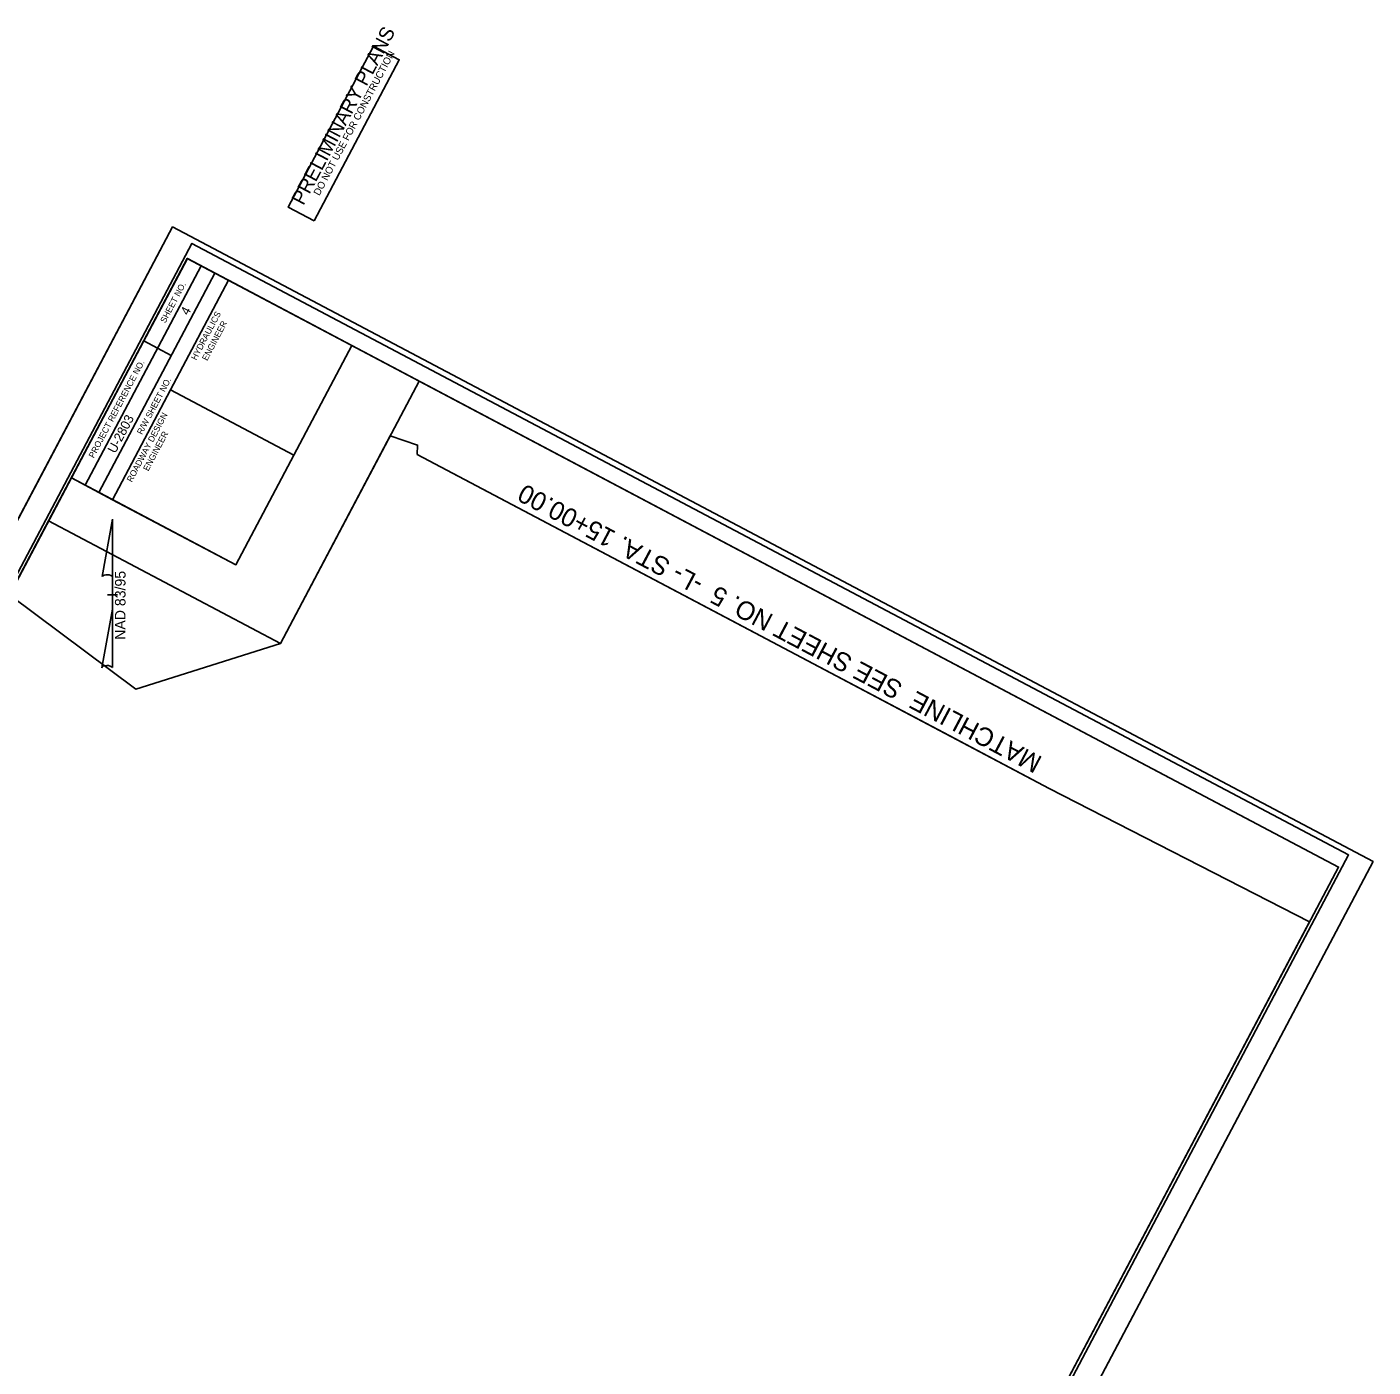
# Model space of a CAD drawing. Extents: x 1974781 to 1976536, y 777153 to 779314.
# Drawn here: x 1975451 to 1976536, y 778233 to 779314 of the extents above; entities that cross this region are included whole.
import ezdxf

# ---------------------------------------------------------------- set-up
doc = ezdxf.new("R2010")
doc.units = 0
for name, color, linetype in [('Matchline', 7, 'Continuous'), ('Matchline Text', 7, 'Continuous'), ('Old_Level_1', 7, 'Continuous'), ('Sheet Clip Boundary CELL', 7, 'Continuous'), ('Sheet Cutting Line CELL', 7, 'Continuous'), ('Sheet Data Field CELL', 7, 'Continuous'), ('Sheet North Arrow Point CELL', 7, 'Continuous'), ('Sheet Plan CELL', 7, 'Continuous'), ('Sheet Plan Layout CELL', 7, 'Continuous'), ('Sheet Plot Border Inside CELL', 7, 'Continuous'), ('Sheet Plot Border Outside CELL', 7, 'Continuous'), ('Sheet Sticker Preliminary CELL', 7, 'Continuous')]:
    doc.layers.add(name, color=color, linetype=linetype)

msp = doc.modelspace()

# ---------------------------------------------------------------- linework, layer by layer
at = {"layer": 'Matchline'}
msp.add_lwpolyline([(1976275.1, 778699.8), (1976019.4, 778834.9), (1975765.3, 778969.2)], dxfattribs=at)
at = {"layer": 'Old_Level_1'}
for p, q in [((1975511.4, 778870.7), (1975519.7, 778917)), ((1975519.8, 778917), (1975519.7, 778917)), ((1975519.8, 778917), (1975519.7, 778917)), ((1975519.8, 778917), (1975519.7, 778869.2)), ((1975519.6, 778844.4), (1975519.7, 778870.6)), ((1975519.7, 778869.2), (1975519.7, 778870.6)), ((1975515.7, 778856), (1975515.6, 778856)), ((1975515.7, 778856), (1975523.7, 778856)), ((1975519.2, 778856), (1975515.7, 778856)), ((1975519.6, 778844.4), (1975511.2, 778797.2)), ((1975519.6, 778797.4), (1975519.6, 778844.4))]:
    msp.add_line(p, q, dxfattribs=at)
for centre, start_param, end_param in [((1975515.6, 778870.2), 0.216388, 2.908219), ((1975515.4, 778797), 0.201328, 3.141593)]:
    msp.add_ellipse(centre, major_axis=(4.23, -0.04), ratio=0.461098, start_param=start_param, end_param=end_param, dxfattribs=at)
at = {"layer": 'Sheet Clip Boundary CELL'}
msp.add_lwpolyline([(1975830.7, 777354.5), (1976484.9, 778592.2), (1976275.1, 778699.8), (1976185.1, 778747.3), (1975765.3, 778969.2), (1975765.7, 778976.7), (1975743.6, 778984.1), (1975655.2, 778816.8), (1975538.6, 778780), (1975436.7, 778856), (1974902.4, 777845.2)], close=True, dxfattribs=at)
at = {"layer": 'Sheet Cutting Line CELL'}
for p, q in [((1975568.1, 779152.7), (1974781.3, 777664.3)), ((1975749.4, 777152.6), (1976536.2, 778640.9))]:
    msp.add_line(p, q, dxfattribs=at)
at = {"layer": 'Sheet North Arrow Point CELL'}
msp.add_line((1975519.2, 778856), (1975519.2, 778856), dxfattribs=at)
at = {"layer": 'Sheet Plan CELL'}
for p, q in [((1975497.6, 778944.4), (1975591.1, 779121.3)), ((1975508.7, 778938.6), (1975602.2, 779115.4)), ((1975508.7, 778938.6), (1975602.2, 779115.4)), ((1975545, 779060.8), (1975567.1, 779049.1)), ((1975566.5, 779021.2), (1975665.9, 778968.6)), ((1975508.7, 778938.6), (1975519.7, 778932.7))]:
    msp.add_line(p, q, dxfattribs=at)
for points in [[(1975580, 779127.2), (1974879, 777801), (1975807.3, 777310.3), (1976508.3, 778636.4)], [(1975486.5, 778950.3), (1975580, 779127.2), (1975602.2, 779115.4), (1975508.7, 778938.6)], [(1975566.5, 779021.2), (1975613.2, 779109.6), (1975712.7, 779057), (1975666, 778968.6)], [(1975807.3, 777310.3), (1974879, 777801), (1975486.5, 778950.3), (1975619.2, 778880.2), (1975712.7, 779057), (1976508.3, 778636.4)], [(1975519.7, 778932.7), (1975566.5, 779021.2), (1975666, 778968.6), (1975619.2, 778880.2)]]:
    msp.add_lwpolyline(points, close=True, dxfattribs=at)
at = {"layer": 'Sheet Plan Layout CELL'}
for points in [[(1975655.2, 778816.8), (1975767, 779028.3), (1975580.1, 779127.2), (1975468.2, 778915.6)], [(1974879, 777801), (1975807.3, 777310.3), (1976508.3, 778636.4), (1975767, 779028.3), (1975655.2, 778816.8), (1975468.2, 778915.6)]]:
    msp.add_lwpolyline(points, close=True, dxfattribs=at)
at = {"layer": 'Sheet Plot Border Inside CELL'}
msp.add_lwpolyline([(1975737.8, 777173.4), (1976516.4, 778646.3), (1975583.7, 779139.4), (1974805.1, 777666.5)], close=True, dxfattribs=at)
at = {"layer": 'Sheet Plot Border Outside CELL'}
msp.add_lwpolyline([(1975749.4, 777152.6), (1976536.2, 778640.9), (1975568.1, 779152.7), (1974781.3, 777664.3)], close=True, dxfattribs=at)
at = {"layer": 'Sheet Sticker Preliminary CELL'}
msp.add_lwpolyline([(1975682.2, 779157.5), (1975661.4, 779168.5), (1975730.1, 779298.5), (1975750.9, 779287.5)], close=True, dxfattribs=at)

# ---------------------------------------------------------------- texts
at = {"layer": 'Matchline Text'}
msp.add_text('MATCHLINE  SEE SHEET NO. 5  -L- STA. 15+00.00', height=15, rotation=152.1381, dxfattribs=at).set_placement((1976270.3, 778724.8))
at = {"layer": 'Old_Level_1'}
msp.add_text('NAD 83/95', height=8.5, rotation=89.9041, dxfattribs=at).set_placement((1975530.1, 778819.7))
at = {"layer": 'Sheet Data Field CELL'}
for s, p in [('4', (1975580.7, 779080.8)), ('U-2803   ', (1975521.9, 778969.5))]:
    msp.add_text(s, height=7.5, rotation=62.1381, dxfattribs=at).set_placement(p)
at = {"layer": 'Sheet Plan CELL'}
for s, p in [('SHEET NO.', (1975562.3, 779074.7)), ('HYDRAULICS', (1975587.2, 779044.7)), ('ENGINEER', (1975596, 779044.3)), ('PROJECT REFERENCE NO.', (1975504.6, 778965.8)), ('R/W SHEET NO.', (1975543.5, 778984.7)), ('ROADWAY DESIGN', (1975535.3, 778946.4)), ('ENGINEER', (1975548.5, 778955.3))]:
    msp.add_text(s, height=5, rotation=62.1381, dxfattribs=at).set_placement(p)
at = {"layer": 'Sheet Sticker Preliminary CELL'}
for s, height, p in [('PRELIMINARY PLANS', 11.52, (1975673.6, 779169.4)), ('DO NOT USE FOR CONSTRUCTION', 5.76, (1975686.5, 779177.4))]:
    msp.add_text(s, height=height, rotation=62.1381, dxfattribs=at).set_placement(p)

doc.saveas('drawing.dxf')
